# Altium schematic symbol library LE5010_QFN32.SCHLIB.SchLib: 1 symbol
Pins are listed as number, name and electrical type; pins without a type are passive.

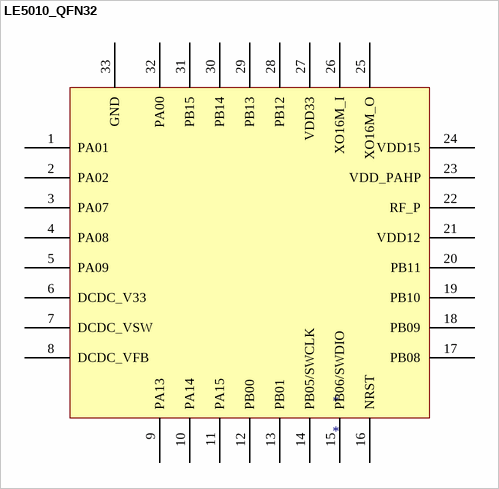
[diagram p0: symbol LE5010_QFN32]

## LE5010_QFN32
designator *
pins: 1 PA01, 2 PA02, 3 PA07, 4 PA08, 5 PA09, 6 DCDC_V33, 7 DCDC_VSW, 8 DCDC_VFB, 9 PA13, 10 PA14, 11 PA15, 12 PB00, 13 PB01, 14 PB05/SWCLK, 15 PB06/SWDIO, 16 NRST, 17 PB08, 18 PB09, 19 PB10, 20 PB11, 21 VDD12, 22 RF_P, 23 VDD_PAHP, 24 VDD15, 25 XO16M_O, 26 XO16M_I, 27 VDD33, 28 PB12, 29 PB13, 30 PB14, 31 PB15, 32 PA00, 33 GND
